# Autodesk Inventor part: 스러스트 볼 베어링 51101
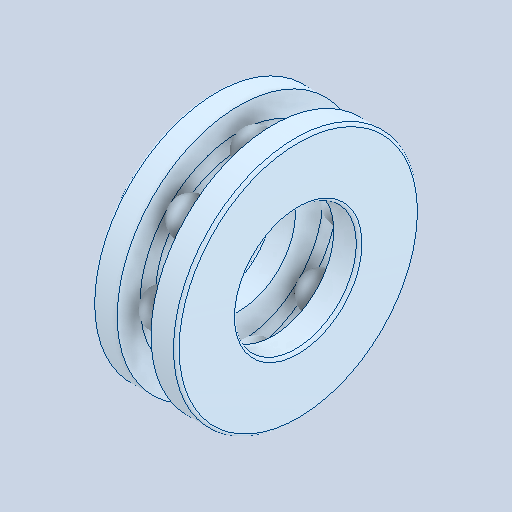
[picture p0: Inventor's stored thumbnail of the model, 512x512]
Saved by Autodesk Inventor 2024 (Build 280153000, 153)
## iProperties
Created: 2024-07
Part Number: 스러스트 볼 베어링 51101
Material: 강철, 연강
Description: 롤링 베어링 - 플랫 뒷면이 있는 스러스트 볼 베어링
Document SubType Name: Modeling
Designer: com
Density: 7.85 g/cm^3
Appearance: 기본값
Author: jhkim
Sending System: Autodesk Inventor 2025
Preprocessor: ST-DEVELOPER v20
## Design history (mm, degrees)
feature "Solid1"
feature "Solid1:1"
feature "Solid1:2"
feature "Solid1:3"
feature "Solid1:4"
feature "Solid1:5"
feature "Solid1:6"
feature "Solid1:7"
feature "Solid1:8"
feature "Solid1:9"
node "솔리드1"
node "솔리드2"
node "솔리드3"
node "솔리드4"
node "솔리드5"
node "솔리드6"
node "솔리드7"
node "솔리드8"
node "솔리드9"
node "솔리드10"
